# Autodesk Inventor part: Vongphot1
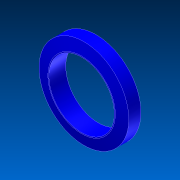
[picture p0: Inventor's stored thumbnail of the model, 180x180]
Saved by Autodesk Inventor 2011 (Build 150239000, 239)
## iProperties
Created: 2011-05
Part Number: Vongphot1
Document SubType Name: Modeling
Designer: 904Chiaki
Density: 1 g/cm^3
Mass: 6.59028 g
Surface Area: 36.9866 cm^2
Volume: 6.59028 cm^3
Author: 904Chiaki
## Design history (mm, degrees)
sketch "Sketch1"
  geometry: L1 (-15.919, 18.279)-(-15.919, -12.371); L2 (8.081, 8.082)-(8.081, 11.332); L3 (8.081, 11.332)-(2.081, 12.582); L4 (8.081, 4.832)-(2.081, 3.582); L5 (8.081, 8.082)-(8.081, 4.832); L6 (1.581, 12.582)-(1.581, 3.582); L7 (2.081, 12.582)-(1.581, 12.582); L8 (2.081, 3.582)-(1.581, 3.582); 1 further point
  constraints: 16 end point
  dimensions: "d11" = 3.25 distance of L2.start L2.end; "d12" = 17.5 distance between parallel lines of L1 L6
revolve "Revolution1" sketch "Sketch1" stored, may be unused: angle "d7" = 90 deg
body "Solid1"
